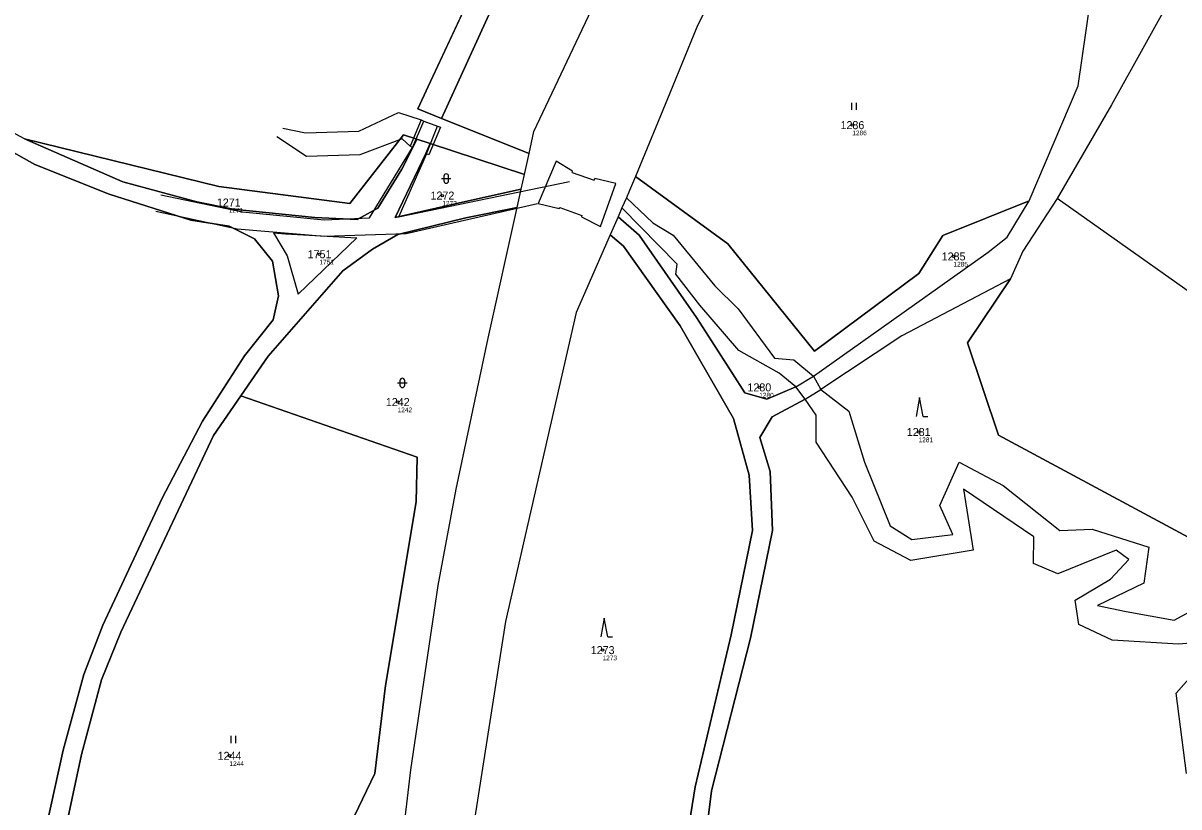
# Model space of a CAD drawing. Extents: x -781091 to -780384, y -1093010 to -1092030.
# Drawn here: x -780836.1 to -780590.6, y -1092424 to -1092257.6 of the extents above; entities that cross this region are included whole.
import ezdxf

# ---------------------------------------------------------------- set-up
doc = ezdxf.new("R2010")
doc.units = 0
for name, color, linetype in [('Vrstva 1', 7, 'Continuous'), ('Vrstva 2', 7, 'Continuous'), ('Vrstva 3', 7, 'Continuous'), ('Vrstva 4', 7, 'Continuous'), ('Vrstva 50', 7, 'Continuous'), ('Vrstva 51', 7, 'Continuous')]:
    doc.layers.add(name, color=color, linetype=linetype)

msp = doc.modelspace()

# ---------------------------------------------------------------- linework, layer by layer
at = {"layer": 'Vrstva 1'}
for p, q in [((-780750.09, -1092271.06), (-780741.07, -1092251.75)), ((-780752.3, -1092275.79), (-780750.09, -1092271.06)), ((-780747.21, -1092277.83), (-780752.3, -1092275.79)), ((-780728.65, -1092285.26), (-780747.21, -1092277.83)), ((-780755.34, -1092281.27), (-780752.49, -1092282.21)), ((-780752.49, -1092282.21), (-780749.63, -1092283.15)), ((-780749.63, -1092283.15), (-780729.64, -1092289.74)), ((-780729.64, -1092289.74), (-780728.65, -1092285.26)), ((-780730.34, -1092292.86), (-780729.64, -1092289.74)), ((-780731.2, -1092296.75), (-780730.34, -1092292.86)), ((-780708.91, -1092296.82), (-780709.74, -1092298.72)), ((-780707.98, -1092294.7), (-780708.91, -1092296.82)), ((-780709.74, -1092298.72), (-780711.41, -1092302.55)), ((-780668.22, -1092332.56), (-780666.71, -1092335.34)), ((-780670.04, -1092337.4), (-780671.97, -1092334.83))]:
    msp.add_line(p, q, dxfattribs=at)
for points in [[(-780747.21, -1092277.83), (-780685.55, -1092142.84), (-780651.37, -1092127.5), (-780647.92, -1092125.01), (-780638.36, -1092118.5)], [(-780728.65, -1092285.26), (-780727.61, -1092280.58), (-780706.42, -1092235.73), (-780693.52, -1092214.87), (-780664.87, -1092169.47), (-780653.5, -1092150.68), (-780657.75, -1092145.05), (-780647.94, -1092137.67), (-780638.36, -1092118.5)], [(-780674.85, -1092221.17), (-780693, -1092258.45), (-780698.75, -1092272.47), (-780706.06, -1092290.15)], [(-780622.45, -1092295.31), (-780612, -1092270.91), (-780608.54, -1092246.82), (-780610.07, -1092234.05)], [(-780591.27, -1092250.31), (-780604.95, -1092274.93), (-780616.5, -1092294.82)], [(-780879.57, -1092264.03), (-780864.65, -1092270.09), (-780848.28, -1092279.36), (-780833.6, -1092287.57), (-780817.83, -1092293.86), (-780800.49, -1092299.43), (-780792.33, -1092300.67), (-780786.97, -1092303.35), (-780783.1, -1092308.11), (-780781.85, -1092315.45), (-780783.01, -1092320.54), (-780789.1, -1092328.24), (-780798.01, -1092342.06), (-780806.54, -1092358.44), (-780819.19, -1092385.38), (-780823.21, -1092395.87), (-780827.6, -1092411.94), (-780833.73, -1092439.91), (-780840.39, -1092483.26), (-780842.9, -1092496.39)], [(-780835.81, -1092282.14), (-780794.56, -1092292.26), (-780766.7, -1092295.88), (-780755.34, -1092281.27)], [(-780835.81, -1092282.14), (-780814.92, -1092291.27), (-780799.2, -1092295.49), (-780791.46, -1092297.09), (-780774.15, -1092298.87), (-780765.16, -1092299.25), (-780760.78, -1092296.86), (-780755.69, -1092288.6), (-780753.24, -1092283.87), (-780752.49, -1092282.21)], [(-780749.63, -1092283.15), (-780750.57, -1092285.27), (-780757.05, -1092298.83), (-780742.78, -1092295.59), (-780730.34, -1092292.86)], [(-780706.06, -1092290.15), (-780707.29, -1092293.11), (-780707.98, -1092294.7)], [(-780622.45, -1092295.31), (-780640.77, -1092302.69), (-780645.88, -1092310.74), (-780668.03, -1092327.21), (-780686.44, -1092304.47), (-780706.06, -1092290.15)], [(-780731.2, -1092296.75), (-780742.04, -1092298.94), (-780756.55, -1092302.48), (-780761.91, -1092305.55), (-780768.18, -1092310.15), (-780784.03, -1092328.26), (-780789.88, -1092336.74)], [(-780759.77, -1092467.15), (-780753.76, -1092416.08), (-780747.98, -1092377), (-780744.13, -1092356.55), (-780737.36, -1092324.44), (-780731.2, -1092296.75)], [(-780671.97, -1092334.83), (-780675.52, -1092331.92), (-780684.11, -1092327.08), (-780692.35, -1092317.43), (-780697.5, -1092310.89), (-780697.2, -1092308.75), (-780708.91, -1092296.82)], [(-780707.98, -1092294.7), (-780702.34, -1092299.97), (-780698.07, -1092302.61), (-780689.21, -1092313.37), (-780684.22, -1092318.24), (-780676.52, -1092328.71), (-780672.43, -1092329.03), (-780668.22, -1092332.56)], [(-780668.22, -1092332.56), (-780651.64, -1092320.77), (-780631.16, -1092306.24), (-780627.08, -1092303.02), (-780622.45, -1092295.31)], [(-780616.5, -1092294.82), (-780623.79, -1092305.99), (-780626.4, -1092311.9)], [(-780384.4, -1092459.05), (-780494.05, -1092381.46), (-780616.5, -1092294.82)], [(-780671.97, -1092334.83), (-780678.14, -1092337.44), (-780682.81, -1092336.08), (-780685.46, -1092331.99), (-780693.12, -1092320.09), (-780705.28, -1092302.57), (-780709.74, -1092298.72)], [(-780711.41, -1092302.55), (-780718.61, -1092319.03), (-780733.66, -1092384.59), (-780743.94, -1092450.08), (-780744.56, -1092454.48), (-780746.39, -1092467.56)], [(-780608.24, -1092548.07), (-780607.24, -1092538.28), (-780608.68, -1092520.39), (-780609.63, -1092517.25), (-780613.68, -1092512.22), (-780621.88, -1092504.68), (-780625, -1092503.07), (-780630.76, -1092500.1), (-780652.02, -1092489.14), (-780674.68, -1092475.17), (-780682.98, -1092467.81), (-780689.3, -1092461.05), (-780694.47, -1092450.12), (-780695.59, -1092433.4), (-780693.4, -1092419.71), (-780685.71, -1092387.42), (-780681.19, -1092365.26), (-780681.9, -1092353.55), (-780685.2, -1092341.5), (-780696.55, -1092321.87), (-780708.62, -1092304.95), (-780711.41, -1092302.55)], [(-780626.4, -1092311.9), (-780649.45, -1092324), (-780666.71, -1092335.34)], [(-780434.43, -1092471.52), (-780444.96, -1092459.56), (-780485.72, -1092440), (-780511.7, -1092415.04), (-780563.24, -1092380.4), (-780628.93, -1092345.03), (-780635.51, -1092325.46), (-780626.4, -1092311.9)], [(-780666.71, -1092335.34), (-780660.77, -1092339.99), (-780657.4, -1092350.76), (-780651.97, -1092364.33), (-780647.33, -1092367.18), (-780638.67, -1092366.17), (-780641.41, -1092360), (-780637.32, -1092350.77), (-780627.95, -1092355.77), (-780615.92, -1092365.3), (-780609.04, -1092365.04), (-780597.02, -1092368.82), (-780598.06, -1092376.49), (-780607.94, -1092381.24), (-780601.82, -1092382.46), (-780591.62, -1092384.31), (-780584.09, -1092380.2)], [(-780789.88, -1092336.74), (-780752.4, -1092349.73), (-780752.63, -1092359.22), (-780759.1, -1092398.21), (-780761.37, -1092416.88), (-780769.23, -1092433.25), (-780805.89, -1092452.23), (-780840.6, -1092503.73)], [(-780789.88, -1092336.74), (-780795.66, -1092345.12), (-780815.35, -1092386.87), (-780819.45, -1092396.97), (-780823.73, -1092412.88), (-780829.63, -1092440.64), (-780836.4, -1092483.88), (-780840.6, -1092503.73)], [(-780670.04, -1092337.4), (-780677, -1092341.17), (-780679.66, -1092345.56), (-780677.41, -1092352.78), (-780676.95, -1092365.26), (-780681.65, -1092388.13), (-780689.87, -1092420.59), (-780691.5, -1092433.75), (-780690.07, -1092448.87), (-780686.01, -1092457.16), (-780679.31, -1092465.51), (-780672.43, -1092471.54), (-780650.1, -1092485.41), (-780622.06, -1092500.13), (-780619.89, -1092501.27), (-780609.27, -1092509.46), (-780605.76, -1092514.29), (-780603.46, -1092520.27), (-780602.65, -1092538.05), (-780599.09, -1092546.21)], [(-780589, -1092416.87), (-780591.25, -1092399.82), (-780581.34, -1092388.68), (-780590.69, -1092389.44), (-780604.84, -1092388.55), (-780611.92, -1092385.28), (-780612.66, -1092380.12), (-780605.16, -1092375.66), (-780601.29, -1092371.45), (-780603.96, -1092369.47), (-780616.37, -1092374.5), (-780621.53, -1092372.29), (-780621.43, -1092366.67), (-780636.39, -1092356.5), (-780634.35, -1092369.5), (-780647.54, -1092371.64), (-780655.34, -1092367.59), (-780660.02, -1092358.25), (-780667.7, -1092346.57), (-780667.65, -1092340.79), (-780670.04, -1092337.4)]]:
    msp.add_lwpolyline(points, dxfattribs=at)
at = {"layer": 'Vrstva 3'}
for p, q in [((-780660.101, -1092275.98), (-780660.101, -1092274.48)), ((-780659.1, -1092275.98), (-780659.1, -1092274.48)), ((-780747.251, -1092290.591), (-780745.249, -1092290.591)), ((-780746.751, -1092290.091), (-780746.751, -1092291.092)), ((-780745.749, -1092291.092), (-780745.749, -1092290.091)), ((-780756.061, -1092333.471), (-780756.061, -1092334.472)), ((-780755.059, -1092334.472), (-780755.059, -1092333.471)), ((-780756.561, -1092333.971), (-780754.559, -1092333.971)), ((-780645.71, -1092337.08), (-780646.46, -1092341.08)), ((-780644.96, -1092341.08), (-780645.71, -1092337.08)), ((-780644.96, -1092341.08), (-780643.964, -1092341.08)), ((-780712.68, -1092383.88), (-780713.43, -1092387.88)), ((-780711.93, -1092387.88), (-780712.68, -1092383.88)), ((-780711.93, -1092387.88), (-780710.934, -1092387.88)), ((-780791.921, -1092410.42), (-780791.921, -1092408.92)), ((-780790.92, -1092410.42), (-780790.92, -1092408.92))]:
    msp.add_line(p, q, dxfattribs=at)
for centre, start, end in [((-780746.25, -1092290.0909), 0, 180), ((-780746.25, -1092291.0909), 180, 359.9878861), ((-780755.56, -1092333.4709), 0, 180), ((-780755.56, -1092334.4709), 180, 359.9878861)]:
    msp.add_arc(centre, 0.5, start, end, dxfattribs=at)
at = {"layer": 'Vrstva 4'}
for p, q in [((-780764.79, -1092280.53), (-780756.36, -1092276.55)), ((-780756.36, -1092276.55), (-780751.53, -1092278.14)), ((-780751.53, -1092278.14), (-780753.87, -1092283.72)), ((-780753.37, -1092283.96), (-780750.99, -1092278.41)), ((-780751.53, -1092278.14), (-780750.99, -1092278.41)), ((-780750.99, -1092278.41), (-780748.08, -1092279.47)), ((-780750.43, -1092285.3), (-780748.08, -1092279.47)), ((-780748.08, -1092279.47), (-780747.46, -1092279.69)), ((-780775.93, -1092285.9), (-780782.19, -1092281.74)), ((-780780.92, -1092279.85), (-780776.1, -1092280.9)), ((-780776.1, -1092280.9), (-780764.79, -1092280.53)), ((-780747.46, -1092279.69), (-780749.96, -1092285.51)), ((-780755.63, -1092282.18), (-780764.62, -1092285.52)), ((-780762.54, -1092298.95), (-780753.37, -1092283.96)), ((-780753.87, -1092283.72), (-780755.63, -1092282.18)), ((-780753.37, -1092283.96), (-780753.87, -1092283.72)), ((-780764.62, -1092285.52), (-780775.93, -1092285.9)), ((-780750.43, -1092285.3), (-780756.4, -1092298.79)), ((-780749.96, -1092285.51), (-780750.43, -1092285.3)), ((-780722.92, -1092286.91), (-780726.74, -1092295.91)), ((-780719.41, -1092289.01), (-780722.92, -1092286.91)), ((-780719.47, -1092289.26), (-780719.41, -1092289.01)), ((-780719.47, -1092289.26), (-780714.84, -1092290.9)), ((-780720.09, -1092291.27), (-780756.4, -1092298.79)), ((-780714.69, -1092290.6), (-780714.84, -1092290.9)), ((-780710.25, -1092291.61), (-780714.69, -1092290.6)), ((-780713.48, -1092300.77), (-780710.25, -1092291.61)), ((-780806.86, -1092294.06), (-780789.51, -1092297.61)), ((-780754.76, -1092302.26), (-780726.82, -1092295.88)), ((-780726.74, -1092295.91), (-780722.25, -1092296.94)), ((-780722.25, -1092296.94), (-780722.1, -1092296.71)), ((-780722.1, -1092296.71), (-780717.42, -1092298.43)), ((-780807.94, -1092297.52), (-780790.67, -1092301.23)), ((-780789.51, -1092297.61), (-780772.14, -1092299.36)), ((-780772.14, -1092299.36), (-780762.54, -1092298.95)), ((-780717.42, -1092298.43), (-780717.49, -1092298.68)), ((-780717.49, -1092298.68), (-780713.48, -1092300.77)), ((-780790.67, -1092301.23), (-780772.13, -1092302.82)), ((-780782.93, -1092302.12), (-780780.03, -1092307)), ((-780782.93, -1092302.12), (-780780.37, -1092302.31)), ((-780780.37, -1092302.31), (-780765.2, -1092303.2)), ((-780777.66, -1092315.15), (-780765.2, -1092303.2)), ((-780772.13, -1092302.82), (-780754.76, -1092302.26)), ((-780780.03, -1092307), (-780777.66, -1092315.15)), ((-780671.97, -1092334.83), (-780668.22, -1092332.56)), ((-780670.04, -1092337.4), (-780666.71, -1092335.34))]:
    msp.add_line(p, q, dxfattribs=at)
at = {"layer": 'Vrstva 50'}
for centre in [(-780660, -1092279.23994), (-780747.07, -1092294.18994), (-780773.16, -1092306.64994), (-780638.51, -1092307.10994), (-780679.76, -1092334.90994), (-780756.56, -1092338.02994), (-780645.92, -1092344.38994), (-780713.04, -1092390.68994), (-780792.28, -1092413.12994)]:
    msp.add_circle(centre, 0.25, dxfattribs=at)
at = {"layer": 'Vrstva 51'}
for points in [[(-780730.47, -1092227.91), (-780741.07, -1092251.75), (-780750.09, -1092271.06), (-780752.3, -1092275.79), (-780747.21, -1092277.83), (-780685.55, -1092142.84), (-780651.37, -1092127.5), (-780647.92, -1092125.01), (-780638.36, -1092118.5), (-780629, -1092099.77), (-780605.74, -1092056.81), (-780592.19, -1092032.25), (-780594.95, -1092031.33), (-780599.65, -1092029.77), (-780651.37, -1092121.46), (-780681.84, -1092130.42), (-780690.61, -1092139.65), (-780712.7, -1092187.91)], [(-780706.42, -1092235.73), (-780693.52, -1092214.87), (-780664.87, -1092169.47), (-780653.5, -1092150.68), (-780657.75, -1092145.05), (-780647.94, -1092137.67), (-780638.36, -1092118.5), (-780647.92, -1092125.01), (-780651.37, -1092127.5), (-780685.55, -1092142.84), (-780747.21, -1092277.83), (-780728.65, -1092285.26), (-780727.61, -1092280.58)], [(-780614.6, -1092222.86), (-780628.85, -1092223.69), (-780640.82, -1092228.27), (-780674.85, -1092221.17), (-780693, -1092258.45), (-780698.75, -1092272.47), (-780706.06, -1092290.15), (-780686.44, -1092304.47), (-780668.03, -1092327.21), (-780645.88, -1092310.74), (-780640.77, -1092302.69), (-780622.45, -1092295.31), (-780612, -1092270.91), (-780608.54, -1092246.82), (-780610.07, -1092234.05)], [(-780774.15, -1092298.87), (-780765.16, -1092299.25), (-780760.78, -1092296.86), (-780755.69, -1092288.6), (-780753.24, -1092283.87), (-780752.49, -1092282.21), (-780755.34, -1092281.27), (-780766.7, -1092295.88), (-780794.56, -1092292.26), (-780835.81, -1092282.14), (-780814.92, -1092291.27), (-780799.2, -1092295.49), (-780791.46, -1092297.09)], [(-780730.34, -1092292.86), (-780729.64, -1092289.74), (-780749.63, -1092283.15), (-780750.57, -1092285.27), (-780757.05, -1092298.83), (-780742.78, -1092295.59)], [(-780631.16, -1092306.24), (-780627.08, -1092303.02), (-780622.45, -1092295.31), (-780640.77, -1092302.69), (-780645.88, -1092310.74), (-780668.03, -1092327.21), (-780686.44, -1092304.47), (-780706.06, -1092290.15), (-780707.29, -1092293.11), (-780707.98, -1092294.7), (-780702.34, -1092299.97), (-780698.07, -1092302.61), (-780689.21, -1092313.37), (-780684.22, -1092318.24), (-780676.52, -1092328.71), (-780672.43, -1092329.03), (-780668.22, -1092332.56), (-780651.64, -1092320.77)], [(-780697.2, -1092308.75), (-780708.91, -1092296.82), (-780709.74, -1092298.72), (-780705.28, -1092302.57), (-780693.12, -1092320.09), (-780685.46, -1092331.99), (-780682.81, -1092336.08), (-780678.14, -1092337.44), (-780671.97, -1092334.83), (-780675.52, -1092331.92), (-780684.11, -1092327.08), (-780692.35, -1092317.43), (-780697.5, -1092310.89)], [(-780494.05, -1092381.46), (-780616.5, -1092294.82), (-780623.79, -1092305.99), (-780626.4, -1092311.9), (-780635.51, -1092325.46), (-780628.93, -1092345.03), (-780563.24, -1092380.4), (-780511.7, -1092415.04), (-780485.72, -1092440), (-780444.96, -1092459.56), (-780434.43, -1092471.52), (-780412.99, -1092468.92), (-780396.51, -1092463.88), (-780384.4, -1092459.05)], [(-780836.4, -1092483.88), (-780840.6, -1092503.73), (-780805.89, -1092452.23), (-780769.23, -1092433.25), (-780761.37, -1092416.88), (-780759.1, -1092398.21), (-780752.63, -1092359.22), (-780752.4, -1092349.73), (-780789.88, -1092336.74), (-780795.66, -1092345.12), (-780815.35, -1092386.87), (-780819.45, -1092396.97), (-780823.73, -1092412.88), (-780829.63, -1092440.64)]]:
    msp.add_lwpolyline(points, close=True, dxfattribs=at)
for points in [[(-780829.63, -1092440.64), (-780823.73, -1092412.88), (-780819.45, -1092396.97), (-780815.35, -1092386.87), (-780795.66, -1092345.12), (-780789.88, -1092336.74), (-780784.03, -1092328.26), (-780768.18, -1092310.15), (-780761.91, -1092305.55), (-780756.55, -1092302.48), (-780742.04, -1092298.94), (-780731.2, -1092296.75), (-780730.34, -1092292.86), (-780742.78, -1092295.59), (-780757.05, -1092298.83), (-780750.57, -1092285.27), (-780749.63, -1092283.15), (-780752.49, -1092282.21), (-780753.24, -1092283.87), (-780755.69, -1092288.6), (-780760.78, -1092296.86), (-780765.16, -1092299.25), (-780774.15, -1092298.87), (-780791.46, -1092297.09), (-780799.2, -1092295.49), (-780814.92, -1092291.27), (-780835.81, -1092282.14), (-780867.63, -1092264.99)], [(-780848.28, -1092279.36), (-780833.6, -1092287.57), (-780817.83, -1092293.86), (-780800.49, -1092299.43), (-780792.33, -1092300.67), (-780786.97, -1092303.35), (-780783.1, -1092308.11), (-780781.85, -1092315.45), (-780783.01, -1092320.54), (-780789.1, -1092328.24), (-780798.01, -1092342.06), (-780806.54, -1092358.44), (-780819.19, -1092385.38), (-780823.21, -1092395.87), (-780827.6, -1092411.94), (-780833.73, -1092439.91), (-780840.39, -1092483.26)], [(-780840.39, -1092483.26), (-780833.73, -1092439.91), (-780827.6, -1092411.94), (-780823.21, -1092395.87), (-780819.19, -1092385.38), (-780806.54, -1092358.44), (-780798.01, -1092342.06), (-780789.1, -1092328.24), (-780783.01, -1092320.54), (-780781.85, -1092315.45), (-780783.1, -1092308.11), (-780786.97, -1092303.35), (-780792.33, -1092300.67), (-780800.49, -1092299.43), (-780817.83, -1092293.86), (-780833.6, -1092287.57), (-780848.28, -1092279.36)], [(-780759.77, -1092467.15), (-780753.76, -1092416.08), (-780747.98, -1092377), (-780744.13, -1092356.55), (-780737.36, -1092324.44), (-780731.2, -1092296.75), (-780742.04, -1092298.94), (-780756.55, -1092302.48), (-780761.91, -1092305.55), (-780768.18, -1092310.15), (-780784.03, -1092328.26), (-780789.88, -1092336.74), (-780752.4, -1092349.73), (-780752.63, -1092359.22), (-780759.1, -1092398.21), (-780761.37, -1092416.88), (-780769.23, -1092433.25)], [(-780691.5, -1092433.75), (-780689.87, -1092420.59), (-780681.65, -1092388.13), (-780676.95, -1092365.26), (-780677.41, -1092352.78), (-780679.66, -1092345.56), (-780677, -1092341.17), (-780670.04, -1092337.4), (-780671.97, -1092334.83), (-780678.14, -1092337.44), (-780682.81, -1092336.08), (-780685.46, -1092331.99), (-780693.12, -1092320.09), (-780705.28, -1092302.57), (-780709.74, -1092298.72), (-780711.41, -1092302.55), (-780708.62, -1092304.95), (-780696.55, -1092321.87), (-780685.2, -1092341.5), (-780681.9, -1092353.55), (-780681.19, -1092365.26), (-780685.71, -1092387.42), (-780693.4, -1092419.71), (-780695.59, -1092433.4)], [(-780695.59, -1092433.4), (-780693.4, -1092419.71), (-780685.71, -1092387.42), (-780681.19, -1092365.26), (-780681.9, -1092353.55), (-780685.2, -1092341.5), (-780696.55, -1092321.87), (-780708.62, -1092304.95), (-780711.41, -1092302.55), (-780718.61, -1092319.03), (-780733.66, -1092384.59), (-780743.94, -1092450.08)], [(-780563.24, -1092380.4), (-780628.93, -1092345.03), (-780635.51, -1092325.46), (-780626.4, -1092311.9), (-780649.45, -1092324), (-780666.71, -1092335.34), (-780660.77, -1092339.99), (-780657.4, -1092350.76), (-780651.97, -1092364.33), (-780647.33, -1092367.18), (-780638.67, -1092366.17), (-780641.41, -1092360), (-780637.32, -1092350.77), (-780627.95, -1092355.77), (-780615.92, -1092365.3), (-780609.04, -1092365.04), (-780597.02, -1092368.82), (-780598.06, -1092376.49), (-780607.94, -1092381.24), (-780601.82, -1092382.46), (-780591.62, -1092384.31), (-780584.09, -1092380.2)], [(-780589, -1092416.87), (-780591.25, -1092399.82), (-780581.34, -1092388.68), (-780590.69, -1092389.44), (-780604.84, -1092388.55), (-780611.92, -1092385.28), (-780612.66, -1092380.12), (-780605.16, -1092375.66), (-780601.29, -1092371.45), (-780603.96, -1092369.47), (-780616.37, -1092374.5), (-780621.53, -1092372.29), (-780621.43, -1092366.67), (-780636.39, -1092356.5), (-780634.35, -1092369.5), (-780647.54, -1092371.64), (-780655.34, -1092367.59), (-780660.02, -1092358.25), (-780667.7, -1092346.57), (-780667.65, -1092340.79), (-780670.04, -1092337.4), (-780677, -1092341.17), (-780679.66, -1092345.56), (-780677.41, -1092352.78), (-780676.95, -1092365.26), (-780681.65, -1092388.13), (-780689.87, -1092420.59), (-780691.5, -1092433.75)]]:
    msp.add_lwpolyline(points, dxfattribs=at)

# ---------------------------------------------------------------- texts
at = {"layer": 'Vrstva 2'}
for s, p in [('1286', (-780662.507, -1092280.09)), ('1272', (-780749.577, -1092295.04)), ('1271', (-780794.947, -1092296.52)), ('1751', (-780775.667, -1092307.5)), ('1285', (-780641.017, -1092307.96)), ('1280', (-780682.267, -1092335.76)), ('1242', (-780759.067, -1092338.88)), ('1281', (-780648.427, -1092345.24)), ('1273', (-780715.547, -1092391.54)), ('1244', (-780794.787, -1092413.98))]:
    msp.add_text(s, height=1.699998, dxfattribs=at).set_placement(p)
at = {"layer": 'Vrstva 50'}
for s, p in [('1286', (-780660, -1092281.396)), ('1271', (-780792.44, -1092297.826)), ('1272', (-780747.07, -1092296.346)), ('1751', (-780773.16, -1092308.806)), ('1285', (-780638.51, -1092309.266)), ('1280', (-780679.76, -1092337.066)), ('1242', (-780756.56, -1092340.186)), ('1281', (-780645.92, -1092346.546)), ('1273', (-780713.04, -1092392.846)), ('1244', (-780792.28, -1092415.286))]:
    msp.add_text(s, height=0.999996, dxfattribs=at).set_placement(p)

doc.saveas('drawing.dxf')
